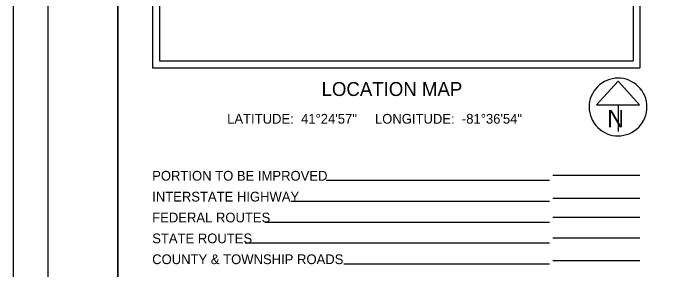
# Model space of a CAD drawing. Extents: x 0 to 42.4, y 0 to 22.
# Drawn here: x 0 to 9.57, y 11.1 to 14.78 of the extents above; entities that cross this region are included whole.
import ezdxf

# ---------------------------------------------------------------- set-up
doc = ezdxf.new("R2010")
doc.units = 0
for name, color, linetype in [('SH_Border', 7, 'Continuous'), ('SH_Cut_Line', 7, 'Continuous'), ('SH_Data', 7, 'Continuous'), ('SH_Text', 7, 'Continuous')]:
    doc.layers.add(name, color=color, linetype=linetype)

msp = doc.modelspace()

# ---------------------------------------------------------------- linework, layer by layer
at = {"layer": 'SH_Border'}
for points in [[(0.5, 21.5), (1.5, 21.5), (1.5, 0.5), (0.5, 0.5)], [(1.5, 21.5), (33.5, 21.5), (33.5, 0.5), (1.5, 0.5)]]:
    msp.add_lwpolyline(points, close=True, dxfattribs=at)
at = {"layer": 'SH_Cut_Line'}
msp.add_lwpolyline([(0, 0), (34, 0), (34, 22), (0, 22)], close=True, dxfattribs=at)
at = {"layer": 'SH_Data'}
for p, q in [((2, 21), (2, 14)), ((9, 21), (9, 14)), ((2.1, 20.9), (2.1, 14.1)), ((8.9, 20.9), (8.9, 14.1)), ((2.1, 14.1), (8.9, 14.1)), ((2.1, 14.1), (2.1, 14.1)), ((2, 14), (9, 14)), ((8.6845, 13.8091), (8.3769, 13.4678)), ((8.9921, 13.4678), (8.6845, 13.8091)), ((8.3769, 13.4678), (8.9921, 13.4678)), ((8.6845, 13.4678), (8.6845, 13.0811)), ((8.6845, 13.4353), (8.6845, 13.4353)), ((8.6845, 13.4353), (8.6845, 13.4353)), ((7.75, 12.4553), (9, 12.4553)), ((7.7, 12.3767), (4.4937, 12.3767)), ((7.7, 12.0767), (3.9895, 12.0767)), ((9, 12.1207), (7.75, 12.1207)), ((7.7, 11.7767), (3.6192, 11.7767)), ((9, 11.8491), (7.75, 11.8491)), ((9, 11.5491), (7.75, 11.5491)), ((7.7, 11.4767), (3.3288, 11.4767)), ((9, 11.2223), (7.75, 11.2223)), ((7.7, 11.1767), (4.7452, 11.1767))]:
    msp.add_line(p, q, dxfattribs=at)
msp.add_arc((8.6845, 13.4353), 0.4148, 129.77984, 129.76332, dxfattribs=at)

# ---------------------------------------------------------------- texts
msp.add_text('N', height=0.25, dxfattribs=at).set_placement((8.5292, 13.144))
at = {"layer": 'SH_Text'}
for s, height, p in [('LOCATION MAP', 0.2, (4.4269, 13.5938)), ('LATITUDE:  41°24\'57"     LONGITUDE:  -81°36\'54"', 0.14, (3.071, 13.1959)), ('PORTION TO BE IMPROVED', 0.14, (1.9944, 12.3767)), ('INTERSTATE HIGHWAY', 0.14, (1.9944, 12.0767)), ('FEDERAL ROUTES', 0.14, (1.9944, 11.7767)), ('STATE ROUTES', 0.14, (1.9944, 11.4767)), ('COUNTY & TOWNSHIP ROADS', 0.14, (1.9944, 11.1767))]:
    msp.add_text(s, height=height, dxfattribs=at).set_placement(p)

doc.saveas('drawing.dxf')
